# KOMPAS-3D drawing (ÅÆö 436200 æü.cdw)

Views: Вид 1, Вид 2
Referenced files in C:\Users\ptitsin\Desktop\Базовая грузовые\: ПТФ 436200.20.001 Плита.cdw
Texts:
  Ra 6,3
  Ra 6,3 ( )
  невидимая2_RGB_0_0_0_SC_1_THICK_0.18
  невидимая2_RGB_0_0_0_SC_1_THICK_0.6
  невидимая2_RGB_255_0_0_SC_1_THICK_0.25
  GOST2.303 6_RGB_255_0_0_SC_1_THICK_0.25
  GOST2.303 5_RGB_255_0_0_SC_1_THICK_0.25
  POLYLINE_STYLE_0.50_RGB_0_0_0
  CONTINUOUS_RGB_255_0_0_THICK_0.25
  ACAD_ISO02W100_RGB_0_0_0_SC_0.5_THICK_0.18
  СONTINUOUS_RGB_0_0_0_THICK_0.18
  ACAD_ISO02W100_RGB_0_0_0_SC_1_THICK_0.18
  CONTINUOUS_RGB_0_0_0_THICK_0.18
  CONTINUOUS_RGB_0_0_0_THICK_0.6
  ACAD_ISO10W100_RGB_0_0_0_SC_1_THICK_0.18
  ПТФ 436200 СБ
  Блок 250т
  Сборочный чертеж
  Т. директор
  ООО "ЗАВОД МАРКОН"
  ПТФ 436200 СБ-
  Блок 250т Сборочный чертеж
Dimensions and other numbers on the sheet: 2; 3; 5; 7; 8; 10; 11; 12; 6; 13; 14; 15; 16; 17; 18; 19; 20; 21; 22; 23; 24; 4; 25; 26; 27; 28; 29; 30; 1; 31; 37; 40; 45; 41; 44; 38; 1:1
